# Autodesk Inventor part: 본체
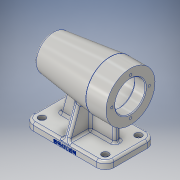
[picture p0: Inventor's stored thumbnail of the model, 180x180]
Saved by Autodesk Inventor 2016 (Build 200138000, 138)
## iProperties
Created: 2018-09
Part Number: 본체
Material: Aluminum 6061
Document SubType Name: Modeling
Designer: CAMTIC
Mass: 732.944 g
Surface Area: 664.383 cm^2
Volume: 271.461 cm^3
Density: 2.7 g/cm^3
Appearance: Aluminum - Flat
Author: CAMTIC
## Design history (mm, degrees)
sketch "Sketch1"
  geometry: L1 (56, -35)-(-56, -35); L2 (-56, -35)-(-56, 35); L3 (-56, 35)-(56, 35); L4 (56, 35)-(56, -35); L5 (0, -49)-(0, 49) reference; L6 (78.4, 0)-(-78.4, 0) reference; 3 further points
  constraints: 8 end point, 2 midpoint, 2 parallel, 2 point on line, 1 horizontal, 1 perpendicular
  dimensions: "d0" = 112 distance of L2.end L3.end; "d1" = 70 distance of L1.end L2.end
extrude "Extrusion1" new body sketch "Sketch1" distance "d2" = 10; taper "d3" = 0 deg
sketch "Sketch3"
  geometry: L1 (56, 108)-(56, 74); L2 (56, 74)-(-56, 74); L3 (56, 108)-(28, 108); L4 (28, 108)-(-52.27, 98.144); L5 (56, 0)-(56, 10) reference; A1 r 80 centre (24, 74) between (-52.27, 98.144) and (-56, 74); 1 further point
  constraints: 8 end point, 2 point on circle, 2 point on line, 1 centre point, 1 horizontal, 1 perpendicular, 1 vertical
  dimensions: "d4" = 160 diameter of A1; "d5" = 7 deg angle of L3 L4; "d6" = 28 distance of L1.start L3.end; "d7" = 112 distance of L2.end L1.end; "d8" = 74 distance from line of L2 point (0, 0); "d9" = 34 distance of L1.start L1.end
revolve "Revolution1" sketch "Sketch3" stored, may be unused: angle "d10" = 90 deg
sketch "Sketch4"
  geometry: L1 (-38, 10)-(-23.173, 65.333); L2 (56, 10)-(-56, 10) reference; L3 (-56, 0)-(-56, 10) reference; L4 (38, 10)-(38, 56.447); L5 (56, 0)-(56, 10) reference; L6 (-23.173, 65.333)-(38, 56.447); L7 (-38, 10)-(38, 10); 1 further point
  constraints: 8 end point, 2 point on line, 1 collinear, 1 vertical
  dimensions: "d12" = 105 deg angle of L2 L1; "d13" = 18 distance from line of L1.start L3; "d14" = 18 distance between parallel lines of L5 L4; "d15" = 46.44721 distance of L4.start L4.end; "d16" = 61.17345 horizontal distance of L1.end L4.end
extrude "Extrusion2" join sketch "Sketch4" stored distance "d17" = 8; taper "d18" = 0 deg
hole "Hole1" diameter "d26" = 42; stored, may be unused: countersink angle "d30" = 90 deg, drill point angle "d32" = 0 deg; dims "d24" = 10, "d25" = 10, "d27" = 6, "d28" = 4, "d29" = 2, "d31" = 15
hole "Hole2" diameter "d35" = 48; stored, may be unused: countersink angle "d39" = 90 deg, drill point angle "d41" = 0 deg; dims "d33" = 10, "d34" = 10, "d36" = 6, "d37" = 4, "d38" = 2, "d40" = 54
hole "Hole3" diameter "d44" = 42; stored, may be unused: countersink angle "d48" = 90 deg, drill point angle "d50" = 0 deg; dims "d42" = 10, "d43" = 10, "d45" = 6, "d46" = 4, "d47" = 2, "d49" = 12
hole "Hole4" diameter "d53" = 35; stored, may be unused: countersink angle "d57" = 90 deg, drill point angle "d59" = 0 deg; dims "d51" = 10, "d52" = 10, "d54" = 6, "d55" = 4, "d56" = 2, "d58" = 18
hole "Hole5" diameter "d62" = 32; stored, may be unused: countersink angle "d66" = 90 deg, drill point angle "d68" = 0 deg; dims "d60" = 10, "d61" = 10, "d63" = 6, "d64" = 4, "d65" = 2, "d67" = 4
hole "Hole6" diameter "d71" = 21; stored, may be unused: countersink angle "d75" = 90 deg, drill point angle "d77" = 0 deg; dims "d69" = 10, "d70" = 10, "d72" = 6, "d73" = 4, "d74" = 2, "d76" = 3
sketch "Sketch6"
  geometry: L1 (0, -95.6)-(0, 55.6) reference; C1 r 10.5 at (0, 0) reference; 2 further points
  constraints: 1 point on line
  dimensions: "d78" = 26 distance of C1.centre point (0, 26)
hole "Hole7" sketch "Sketch6" at (0, 26) diameter "d79" = 3.242; stored, may be unused: countersink angle "d83" = 90 deg, drill point angle "d85" = 118 deg; dims "d80" = 8, "d81" = 4, "d82" = 2, "d84" = 11
pattern_circular "Circular Pattern1" dims angle "d87" = 360 deg
fillet "Fillet1" dims "d89" = 12
fillet "Fillet2" dims "d90" = 0.3
fillet "Fillet3" dims "d91" = 3
fillet "Fillet4" dims "d92" = 3
sketch "Sketch9"
  geometry: L1 (50.889, 19.218)-(8.026, 34.819); L2 (3.022, 34.819)-(3.022, -34.819); L3 (8.026, -34.819)-(50.889, -19.218); L4 (0, 35)-(7, 35) reference; L5 (7, -35)-(0, -35) reference; L6 (-21.6, 0)-(129.6, 0) reference; L7 (10, 4)-(10, -4) reference; L8 (8.026, -34.819)-(3.022, -34.819); L9 (8.026, 34.819)-(3.022, 34.819); L10 (50.889, 19.218)-(44.709, 0); L11 (50.889, -19.218)-(44.709, 0); L12 (0, 23)-(0, -23) reference; A1 r 3 centre (7, 32) between (10, 32) and (7, 35) reference; A2 r 3 centre (7, -32) between (7, -35) and (10, -32) reference; 3 further points
  constraints: 14 end point, 3 point on line, 2 point on circle, 2 tangent, 1 horizontal, 1 midpoint, 1 parallel, 1 vertical
  dimensions: "d93" = 20 deg angle of L4 L1; "d94" = 20 deg angle of L5 L3; "d97" = 6.17925 horizontal distance of L1.start L10.end; "d98" = 92.1759 deg angle of L1 L10; "d99" = 92.1759 deg angle of L3 L11; "d100" = 3.02189 distance between parallel lines of L12 L2
extrude "Extrusion4" join sketch "Sketch9" stored distance "d101" = 8; taper "d102" = 0 deg
fillet "Fillet5" dims "d103" = 3
fillet "Fillet6" dims "d104" = 3
fillet "Fillet7" dims "d105" = 3
fillet "Fillet8" dims "d106" = 3
fillet "Fillet9" dims "d107" = 3
fillet "Fillet10" dims "d108" = 3
fillet "Fillet11" dims "d109" = 3
sketch "Sketch10"
  geometry: A1 r 9 centre (-44, 23) between (-44, 32) and (-53, 23) reference; A2 r 9 centre (-44, -23) between (-53, -23) and (-44, -32) reference; A3 r 9 centre (44, -23) between (44, -32) and (53, -23) reference; A4 r 9 centre (44, 23) between (53, 23) and (44, 32) reference; 5 further points
  constraints: 4 coincident
hole "Hole8" sketch "Sketch10" at (-44, 23), (-44, -23), (44, -23), (44, 23) diameter "d110" = 5.5; stored, may be unused: countersink angle "d114" = 90 deg, drill point angle "d116" = 0 deg; dims "d111" = 8, "d112" = 9.5, "d113" = 5.4, "d115" = 10
workplane "Work Plane1"
sketch "Sketch12"
  geometry: L1 (100, 0)-(100, 7) reference; L2 (44, 21.905)-(44, -2.148); L3 (44, 3)-(15.922, 3); 1 further point
  constraints: 4 end point, 1 horizontal, 1 point on line, 1 vertical, 1 other
  dimensions: "d120" = 3 distance of point (44, 0) L3.start; "d121" = 56 distance from line of L1 L3.start
emboss "Emboss1" sketch "Sketch12" dims "d0" = 112, "d1" = 70, "d122" = 0.5, "d123" = 0
chamfer "Chamfer1" distance "d125" = 1; stored, may be unused: second distance "d126" = 2, angle "d127" = 45 deg
body "Solid1"
other parameters: "d119" = 0.5
